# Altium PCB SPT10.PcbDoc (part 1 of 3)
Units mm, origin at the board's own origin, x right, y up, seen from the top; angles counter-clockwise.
Board outline 194 x 91 mm, 4 copper layers (Top Layer, Mid-Layer 8, Mid-Layer 28, Bottom Layer); 266 components, 1 nets, 803 pads, 630 vias.
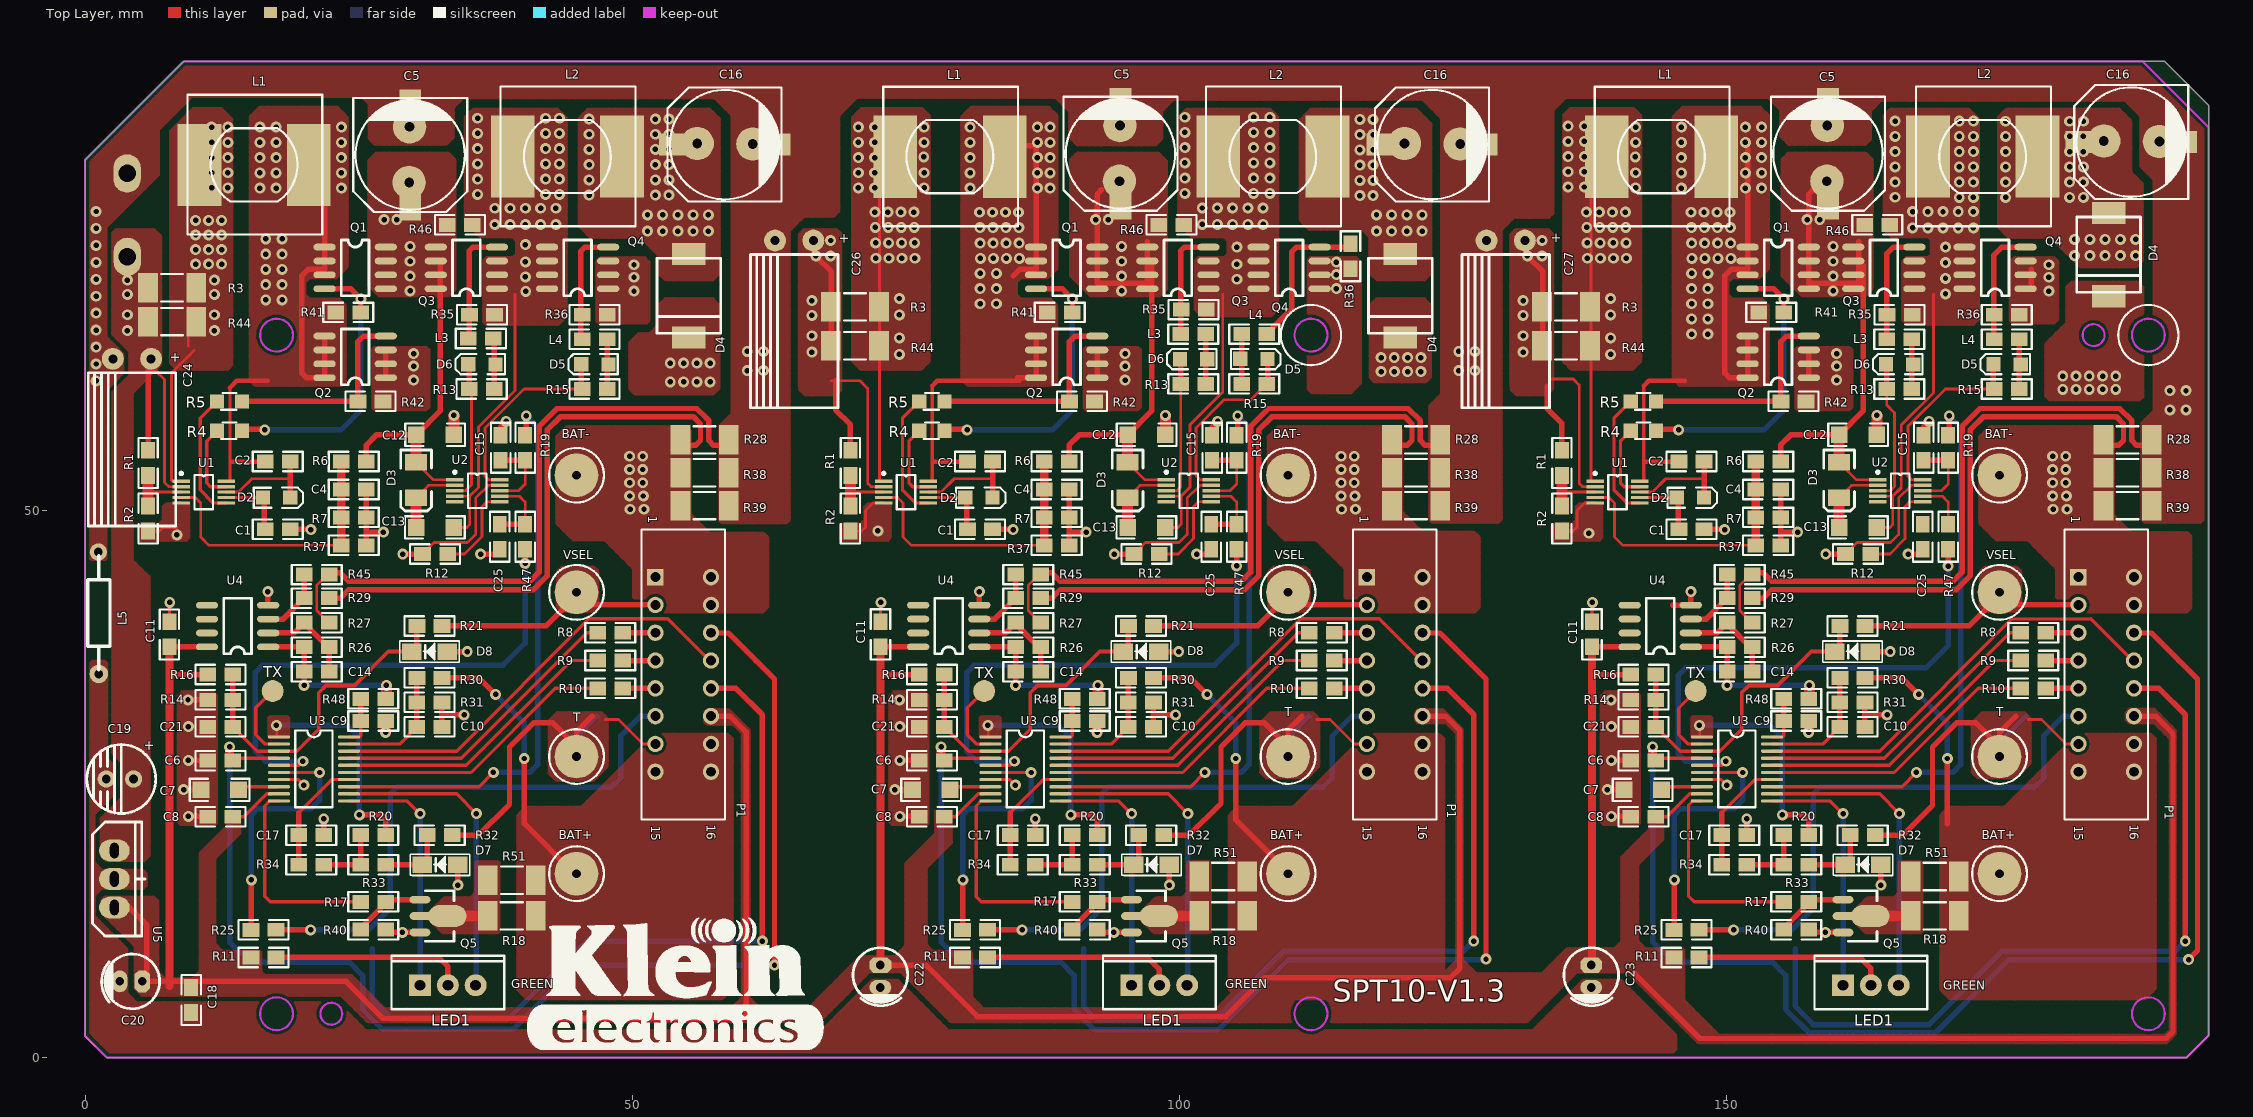
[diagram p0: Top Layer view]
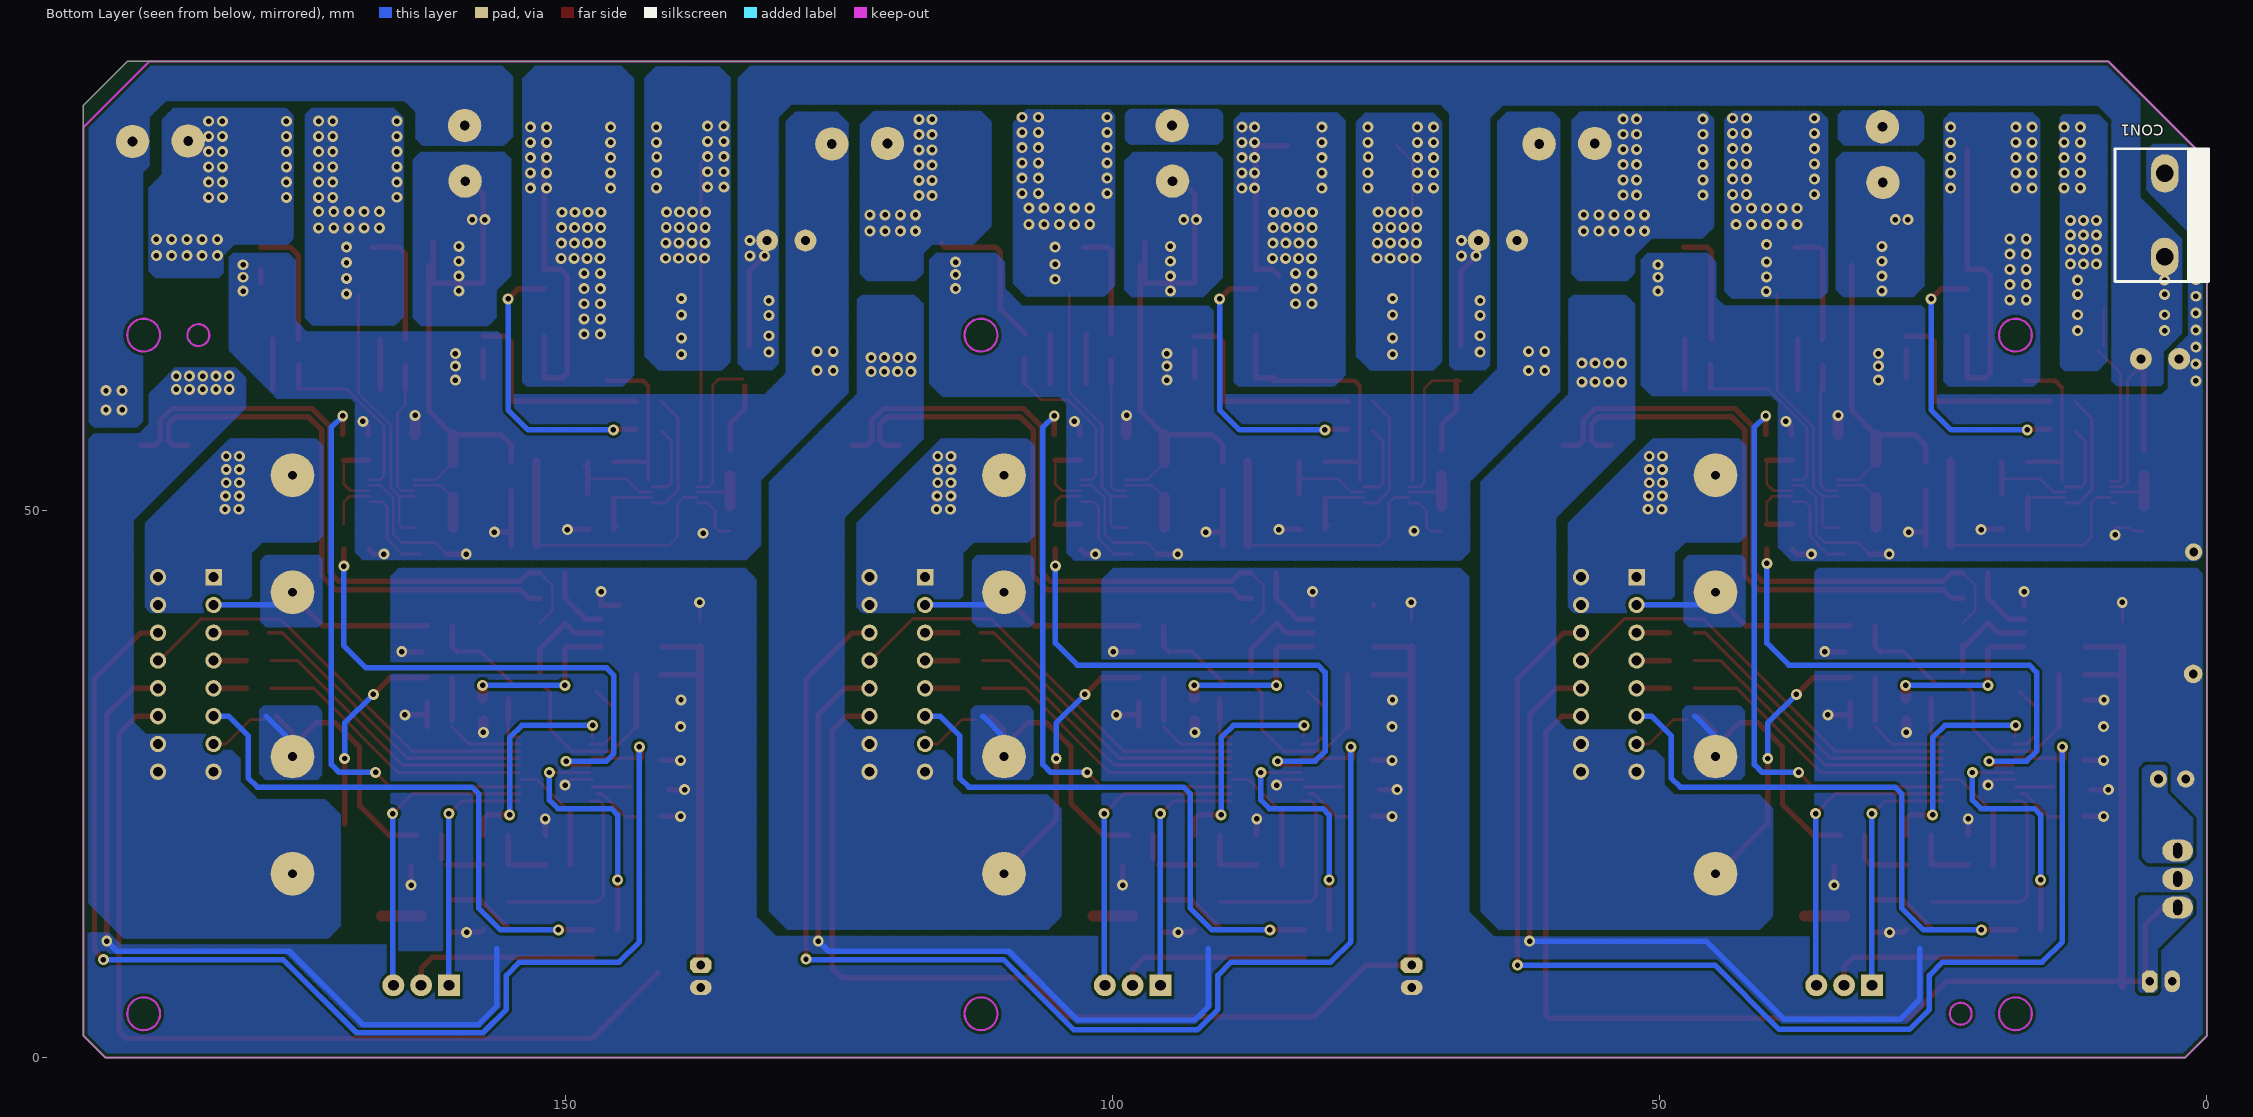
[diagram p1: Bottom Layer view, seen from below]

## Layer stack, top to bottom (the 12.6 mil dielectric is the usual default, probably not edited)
Top Layer: signal copper 0.0356
Dielectric: dielectric 0.32, FR-4, Dk 4.8
Mid-Layer 8: signal copper 0.0356
Dielectric: dielectric 0.32, FR-4, Dk 4.8
Mid-Layer 28: signal copper 0.0356
Dielectric: dielectric 0.32, FR-4, Dk 4.8
Bottom Layer: signal copper 0.0356

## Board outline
2,0 0,2 0,82 9,91 190,91 194,87 194,2 192,0

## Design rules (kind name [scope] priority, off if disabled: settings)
Clearance [All] p1: gap=0.25
DiffPairsRouting [All] p1: maxlimit=0.254 minlimit=0.254 mostfreqgap=0.254 maxuncoupledlength=12.7
FabricationTestPointUsage TestPointUsage [All] p1: valid=0 allowmultiple=FALSE
FabricationTestpoint Testpoint [(IsPad And (OnTopLayer Or OnBottomLayer))] p1: side=3 testpointundercomponent=TRUE minsize=1.016 maxsize=2.54 preferedsize=1.524 minholesize=0 maxholesize=1.016 preferedholesize=0.813 testpointgrid=0.025 allowsidetop=TRUE allowsidebottom=TRUE usegrid=TRUE gridtolerance=0
PolygonConnect [All] p1: connectstyle=Direct reliefconductorwidth=0.254 reliefentries=4 polygonreliefangle="90 Angle"
RoutingVias [All] p1: holewidth=0.711 width=1.27 viastyle="Through Hole" minholewidth=0.711 minwidth=1.27 maxholewidth=0.711 maxwidth=1.27
SilkscreenOverComponentPads [All] p1: minsilkscreentomaskgap=0.254
SolderMaskExpansion [All] p1: expansion=0.102
Width [All] p1: maxlimit=1 minlimit=0.254 preferedwidth=0.5 midlayer8_maxwidth=0.254 midlayer8_prefwidth=0.254 midlayer28_maxwidth=0.254 midlayer28_prefwidth=0.254 minimp=50.000000 maximp=50.000000 favimp=50.000000
24 further rules are at their usual default settings.

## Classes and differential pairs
differential pair NewDifferentialPair1: +"" -""

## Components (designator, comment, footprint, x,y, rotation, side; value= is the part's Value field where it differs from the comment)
C1 "104" 0805 145.621,48.26 r0 top
C1 "104" 0805 80.621,48.26 r0 top
C1 "104" 0805 16.461,48.26 r0 top
C2 "104" 0805 145.621,54.445 r0 top
C2 "104" 0805 80.621,54.445 r0 top
C2 "104" 0805 16.461,54.445 r0 top
C4 "104" 0805 25.7,51.894 r180 top (schematic designator C3)
C4 "104" 0805 89.91,51.894 r180 top (schematic designator C3)
C4 "104" 0805 154.91,51.894 r180 top (schematic designator C3)
C5 "" 10*10.5 159.23,82.56 r270 top
C5 "" 10*10.5 94.6,82.56 r270 top
C5 "" 10*10.5 29.71,82.45 r270 top
C6 "104" 0805 143.51,27.12 r180 top
C6 "104" 0805 78.51,27.12 r180 top
C6 "104" 0805 13.51,27.12 r180 top
C7 "225" 1206 14.02,24.45 r180 top
C7 "225" 1206 144.02,24.45 r180 top
C7 "225" 1206 79.02,24.45 r180 top
C8 "104" 0805 13.51,22 r180 top
C8 "104" 0805 143.51,22 r180 top
C8 "104" 0805 78.51,22 r180 top
C9 "102" 0805 25.19,30.74 r0 top
C9 "102" 0805 90.19,30.74 r0 top
C9 "102" 0805 155.19,30.74 r0 top
C10 "102" 0805 160.32,30.21 r0 top (schematic designator C9)
C10 "102" 0805 95.32,30.21 r0 top (schematic designator C9)
C10 "102" 0805 30.32,30.21 r0 top (schematic designator C9)
C11 "104" 0805 137.677,39.803 r270 top (schematic designator C8)
C11 "104" 0805 72.677,39.803 r270 top (schematic designator C8)
C11 "104" 0805 7.709,39.801 r270 top (schematic designator C8)
C12 "475" 1206 160.272,56.896 r0 top (schematic designator C13)
C12 "475" 1206 95.272,56.896 r0 top (schematic designator C13)
C12 "475" 1206 30.272,56.896 r0 top (schematic designator C13)
C13 "475" 1206 160.25,48.43 r0 top
C13 "475" 1206 95.25,48.43 r0 top
C13 "475" 1206 30.25,48.43 r0 top
C14 "104" 0805 22.31,35.25 r180 top (schematic designator C15)
C14 "104" 0805 87.31,35.25 r180 top (schematic designator C15)
C14 "104" 0805 152.31,35.25 r180 top (schematic designator C15)
C15 "104" 0805 37.969,54.57 r90 top (schematic designator C10)
C15 "104" 0805 167.969,54.57 r90 top (schematic designator C10)
C15 "104" 0805 102.969,54.57 r90 top (schematic designator C10)
C16 "" 10*10.5 186.93,83.63 r180 top
C16 "" 10*10.5 123.05,83.404 r180 top
C16 "" 10*10.5 58.43,83.4 r180 top
C17 "104" 0805 19.526,20.316 r0 top
C17 "104" 0805 149.526,20.316 r0 top
C17 "104" 0805 84.526,20.316 r0 top
C18 "104" 0805 9.7,4.11 r90 top (schematic designator C8)
C19 "Comment" RB.1/.2 3.19,25.442 r0 top
C20 "10μF-50V" "C 5*11" 2.78,6.96 r0 top
C21 "104" 0805 143.51,30.21 r180 top (schematic designator C3)
C21 "104" 0805 78.51,30.21 r180 top (schematic designator C3)
C21 "104" 0805 13.51,30.21 r180 top (schematic designator C3)
C22 "10μF-50V" "C 5*11" 72.66,6 r90 top
C23 "10μF-50V" "C 5*11" 137.6,6 r90 top
C24 "Comment" "RB.1/.2-2 - duplicate" 4.29,63.83 r0 top
C25 "104" 0805 167.89,48.716 r270 top (schematic designator C6)
C25 "104" 0805 102.89,48.716 r270 top (schematic designator C6)
C25 "104" 0805 37.89,48.716 r270 top (schematic designator C6)
C26 "Comment" "RB.1/.2-2 - duplicate" 64.79,74.64 r0 top
C27 "Comment" "RB.1/.2-2 - duplicate" 129.79,74.64 r0 top
CON1 "3.96*3-2" CON2-7.5 3.87,73.15 r270 bottom
D2 "1SS355" SOD-323 16.3,51.16 r90 top
D2 "1SS355" SOD-323 145.46,51.16 r90 top
D2 "1SS355" SOD-323 80.46,51.16 r90 top
D3 "1N5819" SOD-123 160.25,54.37 r270 top
D3 "1N5819" SOD-123 95.25,54.37 r270 top
D3 "1N5819" SOD-123 30.25,54.37 r270 top
D4 "Comment" MBR360 184.87,73.35 r270 top
D4 "Comment" MBR360 120.164,69.596 r270 top
D4 "Comment" MBR360 55.164,69.596 r270 top
D5 "1SS355" SOD-323 47.783,63.32 r270 top
D5 "1SS355" SOD-323 105.587,63.833 r90 top
D5 "1SS355" SOD-323 176.791,63.321 r270 top
D6 "1SS355" SOD-323 37.465,63.32 r270 top
D6 "1SS355" SOD-323 102.477,63.791 r270 top
D6 "1SS355" SOD-323 166.971,63.321 r270 top
D7 "Comment" LL-34 97.461,17.615 r180 top
D7 "Comment" LL-34 162.461,17.615 r180 top
D7 "Comment" LL-34 32.461,17.615 r180 top
D8 "Comment" LL-34 31.49,37.08 r180 top
D8 "Comment" LL-34 96.49,37.08 r180 top
D8 "Comment" LL-34 161.49,37.08 r180 top
L1 "100uH/3A" L 144.016,82.296 r0 top
L1 "100uH/3A" L 79.016,82.296 r0 top
L1 "100uH/3A" L 15.45,81.55 r0 top
L2 "100uH/3A" L 173.37,82.3 r0 top
L2 "100uH/3A" L 108.52,82.3 r0 top
L2 "100uH/3A" L 44.07,82.3 r0 top
L3 "10R" 0805 37.307,65.693 r180 top (schematic designator R13)
L3 "10R" 0805 166.886,65.621 r180 top (schematic designator R13)
L3 "10R" 0805 102.392,66.091 r180 top (schematic designator R13)
L4 "10R" 0805 47.698,65.62 r180 top (schematic designator R14)
L4 "10R" 0805 176.706,65.621 r180 top (schematic designator R14)
L4 "10R" 0805 107.958,66.091 r180 top (schematic designator R14)
L5 "1M" R1/4W 1.27,35.02 r0 top
LED1 "Comment" SFM-T3/X1.6V 163.15,6.604 r0 top
LED1 "Comment" SFM-T3/X1.6V 98.15,6.604 r0 top
LED1 "Comment" SFM-T3/X1.6V 33.15,6.604 r0 top
P1 "Header 8X2" HDR2X8 182.11,43.89 r270 top
P1 "Header 8X2" HDR2X8 117.11,43.89 r270 top
P1 "Header 8X2" HDR2X8 52.11,43.89 r270 top
Q1 "RZC4005S" SOP-8 154.684,72.136 r0 top
Q1 "RZC4005S" SOP-8 89.684,72.136 r0 top
Q1 "RZC4005S" SOP-8 24.684,72.136 r0 top
Q2 "RZC4005S" SOP-8 154.684,64.008 r180 top
Q2 "RZC4005S" SOP-8 89.684,64.008 r180 top
Q2 "RZC4005S" SOP-8 24.684,64.008 r180 top
Q3 "MOSFET-N" SOP-8 164.336,72.136 r180 top
Q3 "MOSFET-N" SOP-8 99.844,72.136 r180 top
Q3 "MOSFET-N" SOP-8 34.844,72.136 r180 top
Q4 "MOSFET-N" SOP-8 174.496,72.136 r180 top
Q4 "MOSFET-N" SOP-8 110,72.136 r180 top
Q4 "MOSFET-N" SOP-8 45.004,72.136 r180 top
Q5 "LC-SOT-89(SOT-89-3)" LC-SOT-89(SOT-89-3) 160.603,12.927 r180 top
Q5 "LC-SOT-89(SOT-89-3)" LC-SOT-89(SOT-89-3) 95.603,12.927 r180 top
Q5 "LC-SOT-89(SOT-89-3)" LC-SOT-89(SOT-89-3) 30.603,12.927 r180 top
R1 "15K" 0805 134.925,53.181 r90 top
R1 "15K" 0805 69.925,53.181 r90 top
R1 "15K" 0805 5.765,53.181 r90 top
R2 "10K" 0805 134.925,48.101 r90 top
R2 "10K" 0805 69.925,48.101 r90 top
R2 "10K" 0805 5.765,48.101 r90 top
R3 "0.01R" 5025[2010] 135.298,68.58 r0 top
R3 "0.01R" 5025[2010] 70.333,68.58 r0 top
R3 "0.01R" 5025[2010] 7.95,70.318 r0 top
R4 "4.3K" 0805-1 141.222,57.262 r0 top
R4 "4.3K" 0805-1 76.222,57.262 r0 top
R4 "4.3K" 0805-1 12.062,57.262 r0 top
R5 "4.3K" 0805-1 141.222,59.943 r0 top
R5 "4.3K" 0805-1 76.222,59.943 r0 top
R5 "4.3K" 0805-1 12.062,59.943 r0 top
R6 "51K" 0805 25.7,54.445 r180 top
R6 "51K" 0805 89.91,54.445 r180 top
R6 "51K" 0805 154.91,54.445 r180 top
R7 "4.3K" 0805 23.414,49.343 r0 top
R7 "4.3K" 0805 87.624,49.343 r0 top
R7 "4.3K" 0805 152.624,49.343 r0 top
R8 "1K" 0805 179.132,38.81 r180 top (schematic designator R10)
R8 "1K" 0805 114.132,38.81 r180 top (schematic designator R10)
R8 "1K" 0805 49.13,38.81 r180 top (schematic designator R10)
R9 "1K" 0805 179.132,36.27 r180 top
R9 "1K" 0805 114.132,36.27 r180 top
R9 "1K" 0805 49.13,36.27 r180 top
R10 "1K" 0805 179.132,33.73 r180 top (schematic designator R8)
R10 "1K" 0805 114.132,33.73 r180 top (schematic designator R8)
R10 "1K" 0805 49.13,33.73 r180 top (schematic designator R8)
R11 "390K1%" 0805 145.164,9.144 r0 top (schematic designator R33)
R11 "390K1%" 0805 80.164,9.144 r0 top (schematic designator R33)
R11 "390K1%" 0805 15.164,9.144 r0 top (schematic designator R33)
R12 "10K" 0805 160.84,46 r0 top
R12 "10K" 0805 95.84,46 r0 top
R12 "10K" 0805 30.84,46 r0 top
R13 "10R" 0805 37.38,61.07 r180 top
R13 "10R" 0805 166.886,61.071 r180 top
R13 "10R" 0805 102.392,61.541 r180 top
R14 "4.3K" 0805 143.51,32.68 r180 top (schematic designator R7)
R14 "4.3K" 0805 78.51,32.68 r180 top (schematic designator R7)
R14 "4.3K" 0805 13.51,32.68 r180 top (schematic designator R7)
R15 "10R" 0805 47.698,61.07 r180 top (schematic designator R13)
R15 "10R" 0805 176.706,61.071 r180 top (schematic designator R13)
R15 "10R" 0805 105.672,61.541 r0 top (schematic designator R13)
R16 "4.3K" 0805 143.51,34.99 r180 top (schematic designator R7)
R16 "4.3K" 0805 78.51,34.99 r180 top (schematic designator R7)
R16 "4.3K" 0805 13.51,34.99 r180 top (schematic designator R7)
R17 "1K" 0805 155.192,14.224 r0 top
R17 "1K" 0805 90.192,14.224 r0 top
R17 "1K" 0805 25.192,14.224 r0 top
R18 "75R/2W" 5025[2010] 168.986,12.942 r180 top
R18 "75R/2W" 5025[2010] 103.986,12.942 r180 top
R18 "75R/2W" 5025[2010] 38.986,12.942 r180 top
R19 "10K" 0805 40.209,56.856 r270 top (schematic designator R12)
R19 "10K" 0805 170.209,56.856 r270 top (schematic designator R12)
R19 "10K" 0805 105.209,56.856 r270 top (schematic designator R12)
R20 "1K" 0805 27.478,20.316 r180 top (schematic designator R15)
R20 "1K" 0805 157.478,20.316 r180 top (schematic designator R15)
R20 "1K" 0805 92.478,20.316 r180 top (schematic designator R15)
R21 "15K" 0805 32.61,39.43 r180 top (schematic designator R1)
R21 "15K" 0805 97.61,39.43 r180 top (schematic designator R1)
R21 "15K" 0805 162.61,39.43 r180 top (schematic designator R1)
R25 "1K" 0805 17.45,11.67 r180 top (schematic designator R15)
R25 "1K" 0805 82.45,11.67 r180 top (schematic designator R15)
R25 "1K" 0805 147.45,11.67 r180 top (schematic designator R15)
R26 "2.4K" 0805 20.024,37.49 r0 top (schematic designator R27)
R26 "2.4K" 0805 85.024,37.49 r0 top (schematic designator R27)
R26 "2.4K" 0805 150.024,37.49 r0 top (schematic designator R27)
R27 "1K" 0805 20.024,39.73 r0 top (schematic designator R29)
R27 "1K" 0805 85.024,39.73 r0 top (schematic designator R29)
R27 "1K" 0805 150.024,39.73 r0 top (schematic designator R29)
R28 "0.1R1%" 5025[2010] 56.605,56.43 r180 top
R28 "0.1R1%" 5025[2010] 121.605,56.43 r180 top
R28 "0.1R1%" 5025[2010] 186.605,56.43 r180 top
R29 "1K" 0805 20.024,41.97 r0 top
R29 "1K" 0805 85.024,41.97 r0 top
R29 "1K" 0805 150.024,41.97 r0 top
R30 "20K1%" 0805 162.61,34.69 r180 top
R30 "20K1%" 0805 97.61,34.69 r180 top
R30 "20K1%" 0805 32.61,34.69 r180 top
R31 "10K1%" 0805 160.32,32.45 r0 top
R31 "10K1%" 0805 95.32,32.45 r0 top
R31 "10K1%" 0805 30.32,32.45 r0 top
R32 "20K" 0805 33.542,20.316 r180 top
R32 "20K" 0805 163.542,20.316 r180 top
R32 "20K" 0805 98.542,20.316 r180 top
R33 "390K1%" 0805 25.192,17.61 r0 top
R33 "390K1%" 0805 155.192,17.61 r0 top
R33 "390K1%" 0805 90.192,17.61 r0 top
R34 "15K1%" 0805 19.526,17.615 r0 top
R34 "15K1%" 0805 149.526,17.615 r0 top
R34 "15K1%" 0805 84.526,17.615 r0 top
R35 "20K" 0805 37.41,67.86 r180 top
R35 "20K" 0805 166.916,67.861 r180 top
R35 "20K" 0805 102.422,68.331 r180 top
R36 "20K" 0805 115.61,72.06 r90 top
R36 "20K" 0805 47.698,67.86 r180 top
R36 "20K" 0805 176.706,67.861 r180 top
R37 "调整" 0805 23.414,46.792 r0 top
R37 "调整" 0805 87.624,46.792 r0 top
R37 "调整" 0805 152.624,46.792 r0 top
R38 "0.1R1%" 5025[2010] 56.605,53.425 r180 top (schematic designator R28)
R38 "0.1R1%" 5025[2010] 121.605,53.425 r180 top (schematic designator R28)
R38 "0.1R1%" 5025[2010] 186.605,53.425 r180 top (schematic designator R28)
R39 "0.1R1%" 5025[2010] 56.61,50.42 r180 top (schematic designator R28)
R39 "0.1R1%" 5025[2010] 121.61,50.42 r180 top (schematic designator R28)
R39 "0.1R1%" 5025[2010] 186.605,50.42 r180 top (schematic designator R28)
R40 "10K" 0805 157.478,11.684 r180 top
R40 "10K" 0805 92.478,11.684 r180 top
R40 "10K" 0805 27.478,11.684 r180 top
R41 "20K" 0805 155.192,68.072 r180 top
R41 "20K" 0805 90.192,68.072 r180 top
R41 "20K" 0805 25.192,68.072 r180 top
R42 "20K" 0805 157.224,59.944 r180 top
R42 "20K" 0805 92.224,59.944 r180 top
R42 "20K" 0805 27.224,59.944 r180 top
R44 "0.01R" 5025[2010] 135.298,65.024 r0 top (schematic designator R3)
R44 "0.01R" 5025[2010] 70.333,65.024 r0 top (schematic designator R3)
R44 "0.01R" 5025[2010] 7.95,67.238 r0 top (schematic designator R3)
R45 "104" 0805 152.31,44.12 r180 top (schematic designator C15)
R45 "104" 0805 87.31,44.12 r180 top (schematic designator C15)
R45 "104" 0805 22.31,44.12 r180 top (schematic designator C15)
R46 "20K" 0805 164.882,76.07 r180 top (schematic designator R35)
R46 "20K" 0805 100.39,76.07 r180 top (schematic designator R35)
R46 "20K" 0805 35.39,76.07 r180 top (schematic designator R35)
R47 "10K" 0805 170.21,46.43 r90 top (schematic designator R12)
R47 "10K" 0805 105.21,46.43 r90 top (schematic designator R12)
R47 "10K" 0805 40.21,46.43 r90 top (schematic designator R12)
R48 "1K" 0805 27.476,32.77 r180 top (schematic designator R15)
R48 "1K" 0805 92.476,32.77 r180 top (schematic designator R15)
R48 "1K" 0805 157.476,32.77 r180 top (schematic designator R15)
R51 "75R/2W" 5025[2010] 168.986,16.54 r180 top (schematic designator R18)
R51 "75R/2W" 5025[2010] 103.986,16.54 r180 top (schematic designator R18)
R51 "75R/2W" 5025[2010] 38.99,16.19 r180 top (schematic designator R18)
U1 "RZC6295" MS10 140.005,51.657 r270 top
U1 "RZC6295" MS10 75.005,51.657 r270 top
U1 "RZC6295" MS10 10.845,51.657 r270 top
U2 "FD2204M" MS10 165.84,51.776 r270 top
U2 "FD2204M" MS10 100.84,51.776 r270 top
U2 "FD2204M" MS10 35.84,51.776 r270 top
U3 "Comment" SSOP20 150.917,26.366 r0 top
U3 "Comment" SSOP20 85.917,26.366 r0 top
U3 "Comment" SSOP20 20.917,26.366 r0 top
U4 "LM358" SOP-8 143.908,39.422 r180 top (schematic designator U103)
U4 "LM358" SOP-8 78.908,39.422 r180 top (schematic designator U103)
U4 "LM358" SOP-8 13.94,39.42 r180 top (schematic designator U103)
U5 "P12NM60FP" TO-220FM 2.68,16.31 r270 top

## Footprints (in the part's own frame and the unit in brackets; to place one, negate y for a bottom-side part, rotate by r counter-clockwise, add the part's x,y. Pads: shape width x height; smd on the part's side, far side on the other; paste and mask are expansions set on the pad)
10*10.5 [mm]
  rect 3.6x2 smd: 1(-4.2,0) 2(4.2,0)
  silkscreen extent -5.21,-5.21 5.21,5.21
0805 [mil]
  rect 60x50 smd: 1(-0.01,-0.01) 2(89.99,0.03)
  silkscreen extent -45,-35 135,35
0805-1 [mm]
  rect 1.3x1.3 smd: 1(0,0) 2(2.286,0)
  silkscreen extent 0.38,-0.76 1.78,0.76
1206 [mil]
  rect 60x60 smd: 1(0,0) 2(135,0)
  silkscreen extent -40,-40 175,40
5025[2010] [mm] "Chip Resistor; Body 5.0 x 2.5 mm (LxW typ)"
  rect 1.8x2.7 smd: 1(-2.2,0) 2(2.2,0)
  silkscreen extent -1,-1.25 1,1.25
"C 5*11" [mm]
  oct 1.4x2 hole 0.8: 1(2.446,0)
  oval 1.4x2 hole 0.8: 2(0.4,0)
  silkscreen extent -1.26,-2.5 4.04,2.5
CON2-7.5 [mm]
  oval 3.5x2.5 hole 1.6: 1(0,0) 2(-7.62,0.025)
  silkscreen extent -9.88,-4.55 2.26,4.03
HDR2X8 [mm] "Connector; Header; 8x2 Position"
  rect 1.5x1.5 hole 0.9: 1(0,0)
  round 1.5 hole 0.9: 2(0,5.08) 3(2.54,0) 4(2.54,5.08) 5(5.08,0) 6(5.08,5.08) 7(7.62,0) 8(7.62,5.08) 9(10.16,0) 10(10.16,5.08) 11(12.7,0) 12(12.7,5.08) 13(15.24,0) 14(15.24,5.08) 15(17.78,0) 16(17.78,5.08)
  silkscreen extent -4.36,-1.27 22.14,6.35
L [mm]
  rect 4x7.5 smd: 1(-5,0) 2(5,0)
  silkscreen extent -6.1,-6.35 6.22,6.4
LC-SOT-89(SOT-89-3) [mm]
  oval 1.9x0.7 smd: 1(0,-1.5) 3(0,1.5)
  oval 2.1x0.7 smd: 2(-0.1,0)
  oval 3.5x2 smd: 2/2(-2.5,0)
  silkscreen extent -3.1,-2.3 -0.5,2.3
LL-34 [mm]
  rect 1.8x1.524 smd: 1(-1.6,0) 2(1.65,0)
  silkscreen extent -2.69,-0.97 2.74,0.98
MBR360 [mil]
  rect 80x120 smd: 1(-150,0) 2(150,0)
  silkscreen extent -135,-115 135,115
MS10 [mm]
  rect 0.3x1.6 smd: 1(-1,-2.05) 2(-0.5,-2.05) 3(0,-2.05) 4(0.5,-2.05) 5(1,-2.05) 6(1,2.05) 7(0.5,2.05) 8(0,2.05) 9(-0.5,2.05) 10(-1,2.05)
  silkscreen extent -1.82,-2.17 1.57,0.85
R1/4W [mm]
  round 1.575 hole 0.8: ""(-0.05,11.163)
  round 1.7 hole 0.8: ""(-0.01,0.023)
  silkscreen extent -1.02,0.38 1.02,10.82
RB.1/.2 [mil]
  round 62 hole 32: 1(49.21,0) 2(-49.21,0)
  silkscreen extent -119,-124 129,124
"RB.1/.2-2 - duplicate" [mm]
  round 2 hole 0.813: 1(1.75,0) 2(-1.75,0)
  silkscreen extent -4,-15.27 4,-1.27
SFM-T3/X1.6V [mm]
  rect 2x2 hole 1: 1(-2.54,0)
  round 2 hole 1: 2(0,0) 3(2.54,0)
  silkscreen extent -5.15,-2.2 5.15,2.7
SOD-123 [mm]
  rect 1.5x2 smd: 1(0,0) 2(3.22,0)
  silkscreen extent -1.14,-1.4 4.45,1.4
SOD-323 [mm]
  rect 1.3x1.3 smd: 1(0,0.045) 2(-0.007,-2.444)
  silkscreen extent -0.95,-3.62 0.9,0.89
SOP-8 [mil]
  oval 80x24 smd: 1(-110,75) 2(-110,25) 3(-110,-25) 4(-110,-75) 5(110,-75) 6(110,-25) 7(110,25) 8(110,75)
  silkscreen extent -50,-100 50,100
SSOP20 [mm]
  oval 2.032x0.3 smd: 1(-3.2,2.925) 2(-3.2,2.275) 3(-3.2,1.625) 4(-3.2,0.975) 5(-3.2,0.325) 6(-3.2,-0.325) 7(-3.2,-0.975) 8(-3.2,-1.625) 9(-3.2,-2.275) 10(-3.2,-2.925) 11(3.2,-2.925) 12(3.2,-2.275) 13(3.2,-1.625) 14(3.2,-0.975) 15(3.2,-0.325) 16(3.2,0.325) 17(3.2,0.975) 18(3.2,1.625) 19(3.2,2.275) 20(3.2,2.925)
  silkscreen extent -1.7,-3.5 1.7,3.5
TO-220FM [mm]
  oval 2x2.8 hole 0.8 slot 1.4 at 0 deg: 1(-2.6,0) 2(0,0) 3(2.6,0)
  silkscreen extent -5.2,-2 5.2,2.79

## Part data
C1 C1 C1 C2 C2 C2 C4 C4 C4 C6 C6 C6 C7 C7 C7 C8 C8 C8 C9 C9 C9 C10 C10 C10 C11 C11 C11 C12 C12 C12 C13 C13 C13 C14 C14 C14 C15 C15 C15 C17 C17 C17 C18 C21 C21 C21 C25 C25 C25 R45 R45 R45: library part Cap, "Capacitor"
C5 C5 C5 C16 C16 C16: library part "Cap Pol1", "Polarized Capacitor (Radial)"
D3 D3 D3: library part "Diode 1N914", "High Conductance Fast Diode"
L1 L1 L1 L2 L2 L2: library part Inductor, "Inductor"
L3 L3 L3 L4 L4 L4 R1 R1 R1 R2 R2 R2 R3 R3 R3 R6 R6 R6 R7 R7 R7 R8 R8 R8 R9 R9 R9 R10 R10 R10 R11 R11 R11 R12 R12 R12 R13 R13 R13 R14 R14 R14 R15 R15 R15 R16 R16 R16 R17 R17 R17 R18 R18 R18 R19 R19 R19 R20 R20 R20 R21 R21 R21 R25 R25 R25 R26 R26 R26 R27 R27 R27 R28 R28 R28 R29 R29 R29 R30 R30 R30 R31 R31 R31 R32 R32 R32 R33 R33 R33 R34 R34 R34 R35 R35 R35 R36 R36 R36 R37 R37 R37 R38 R38 R38 R39 R39 R39 R40 R40 R40 R41 R41 R41 R42 R42 R42 R44 R44 R44 R46 R46 R46 R47 R47 R47 R48 R48 R48 R51 R51 R51: library part Res1, "Resistor"
LED1 LED1 LED1: library part Diac-NPN
P1 P1 P1: "Header, 8-Pin, Dual row"
Q1 Q1 Q1 Q2 Q2 Q2: library part MOSFET-N, "N-Channel MOSFET"
Q3 Q3 Q3 Q4 Q4 Q4: "N-Channel MOSFET"
U4 U4 U4: library part LMV321

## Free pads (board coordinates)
  round 2 smd: 0(17.14,33.48) 0(82.14,33.48) 0(147.14,33.48)
  round 3.048 hole 0.889: 2(29.61,79.95) 2(29.654,85.03) 2(55.93,83.5) 2(61.01,83.456) 2(94.5,80.06) 2(94.544,85.14) 2(120.55,83.504) 2(125.63,83.46) 2(159.13,80.06) 2(159.174,85.14) 2(184.43,83.73) 2(189.51,83.686)
  round 4 hole 0.8: BAT+(44.9,16.8) BAT+(109.9,16.8) BAT+(174.9,16.8) BAT-(44.9,53.2) BAT-(109.9,53.2) BAT-(174.9,53.2) T(44.9,27.5) T(109.9,27.5) T(174.9,27.5) VSEL(44.9,42.5) VSEL(109.9,42.5) VSEL(174.9,42.5)

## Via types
v1: diameter 1, hole 0.5, Top Layer to Bottom Layer, 627 vias
v2: diameter 1, hole 0.5, Top Layer to Bottom Layer, tented top, 3 vias

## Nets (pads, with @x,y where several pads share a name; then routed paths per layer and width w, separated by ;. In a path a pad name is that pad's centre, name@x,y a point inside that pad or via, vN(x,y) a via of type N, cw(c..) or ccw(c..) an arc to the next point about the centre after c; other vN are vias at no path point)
NewNet: P1.14@57.19,28.65 P1.15@52.11,26.11 P1.16@57.19,26.11 pad.BAT+@44.9,16.8 R18.1@41.186,12.942 R51.1@41.19,16.19 | length 12.5
  Top Layer w0.5: 40.13,27.32 40.13,21.362 pad.BAT+@44.75,16.742
pads on no net: C1.1 C1.2 C2.1 C2.2 C4.1 C4.2 C5.1 C5.2 C6.1 C6.2 C7.1 C7.2 C8.1 C8.2 C9.1 C9.2 C10.1 C10.2 C11.1 C11.2 C12.1 C12.2 C13.1 C13.2 C14.1 C14.2 C15.1 C15.2 C16.1 C16.2 C17.1 C17.2 C18.1 C18.2 C19.1 C19.2 C20.1 C20.2 C21.1 C21.2 C22.1 C22.2 C23.1 C23.2 C24.1 C24.2 C25.1 C25.2 C26.1 C26.2 C27.1 C27.2 CON1.1 CON1.2 D2.1 D2.2 D3.1 D3.2 D4.1 D4.2 D5.1 D5.2 D6.1 D6.2 D7.1 D7.2 D8.1 D8.2 L1.1 L1.2 L2.1 L2.2 L3.1 L3.2 L4.1 L4.2 L5. LED1.1 LED1.2 LED1.3 P1.1 P1.2 P1.3 P1.4 P1.5 P1.6 P1.7 P1.8 P1.9 P1.10 P1.11 P1.12 P1.13 P1.14@122.19,28.65 P1.14@187.19,28.65 P1.15@117.11,26.11 P1.15@182.11,26.11 P1.16@122.19,26.11 P1.16@187.19,26.11 Q1.1 Q1.2 Q1.3 Q1.4 Q1.5 Q1.6 Q1.7 Q1.8 Q2.1 Q2.2 Q2.3 Q2.4 Q2.5 Q2.6 Q2.7 Q2.8 Q3.1 Q3.2 Q3.3 Q3.4 Q3.5 Q3.6 Q3.7 Q3.8 Q4.1 Q4.2 Q4.3 Q4.4 Q4.5 Q4.6 Q4.7 Q4.8 Q5.1 Q5.2 Q5.2/2 Q5.3 R1.1 R1.2 R2.1 R2.2 R3.1 R3.2 R4.1 R4.2 R5.1 R5.2 R6.1 R6.2 R7.1 R7.2 R8.1 R8.2 R9.1 R9.2 R10.1 R10.2 R11.1 R11.2 R12.1 R12.2 R13.1 R13.2 R14.1 R14.2 R15.1 R15.2 R16.1 R16.2 R17.1 R17.2 R18.1@106.186,12.942 R18.1@171.186,12.942 R18.2 R19.1 R19.2 R20.1 R20.2 R21.1 R21.2 R25.1 R25.2 R26.1 R26.2 R27.1 R27.2 R28.1 R28.2 R29.1 R29.2 R30.1 R30.2 R31.1 R31.2 R32.1 R32.2 R33.1 R33.2 R34.1 R34.2 R35.1 R35.2 R36.1 R36.2 R37.1 R37.2 R38.1 R38.2 R39.1 R39.2 R40.1 R40.2 R41.1 R41.2 R42.1 R42.2 R44.1 R44.2 R45.1 R45.2 R46.1 R46.2 R47.1 R47.2 R48.1 R48.2 R51.1@106.186,16.54 R51.1@171.186,16.54 R51.2 U1.1 U1.2 U1.3 U1.4 U1.5 U1.6 U1.7 U1.8 U1.9 U1.10 U2.1 U2.2 U2.3 U2.4 U2.5 U2.6 U2.7 U2.8 U2.9 U2.10 U3.1 U3.2 U3.3 U3.4 U3.5 U3.6 U3.7 U3.8 U3.9 U3.10 U3.11 U3.12 U3.13 U3.14 U3.15 U3.16 U3.17 U3.18 U3.19 U3.20 U4.1 U4.2 U4.3 U4.4 U4.5 U4.6 U4.7 U4.8 U5.1 U5.2 U5.3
